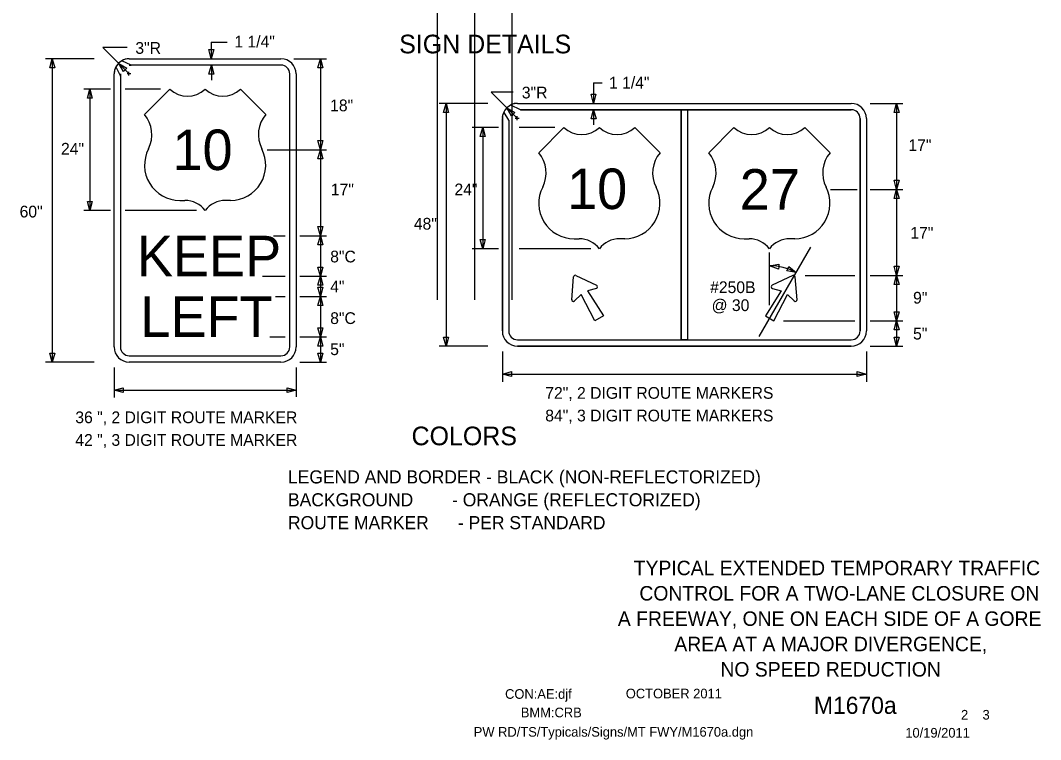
# Model space of a CAD drawing. Extents: x 16715 to 19504, y 7040 to 8495.
# Drawn here: x 17808 to 18464, y 7218 to 7680 of the extents above; entities that cross this region are included whole.
import ezdxf

# ---------------------------------------------------------------- set-up
doc = ezdxf.new("R2010")
doc.units = 0
for name, color, linetype in [('ALI_LEGAL_EX', 7, 'Continuous'), ('BORDER', 7, 'Continuous'), ('BORDER_SIGNAL_WO', 7, 'Continuous'), ('TRAFFIC_SIGNS_PR', 7, 'Continuous'), ('TYPICAL_EX', 7, 'Continuous'), ('TYPICAL_TEXT_DIMEN_PR', 7, 'Continuous')]:
    doc.layers.add(name, color=color, linetype=linetype)

msp = doc.modelspace()

# ---------------------------------------------------------------- linework, layer by layer
at = {"layer": 'ALI_LEGAL_EX'}
for p, q in [((18076.31, 7500.83), (18076.31, 8111.03)), ((18100.31, 7500.83), (18100.31, 8111.03)), ((18124.31, 7500.83), (18124.31, 8111.03))]:
    msp.add_line(p, q, dxfattribs=at)
at = {"layer": 'TRAFFIC_SIGNS_PR'}
for p, q in [((17879.37, 7651.62), (17873.27, 7654.37)), ((17878.16, 7655.69), (17975.66, 7655.69)), ((17868.41, 7470.44), (17868.41, 7645.94)), ((17870.58, 7652.07), (17869.58, 7650.56)), ((17869.6, 7650.49), (17872.48, 7644.45)), ((17872.48, 7645.94), (17872.48, 7470.44)), ((17975.66, 7651.62), (17878.16, 7651.62)), ((17981.35, 7470.44), (17981.35, 7645.94)), ((17985.41, 7645.94), (17985.41, 7470.44)), ((18127.69, 7626.99), (18342.19, 7626.99)), ((18127.69, 7626.99), (18342.19, 7626.99)), ((18118.85, 7621.25), (18121.99, 7616.2)), ((18129.64, 7622.94), (18123.41, 7625.95)), ((18129.62, 7622.93), (18232.9, 7622.93)), ((18342.19, 7622.93), (18129.62, 7622.93)), ((18232.9, 7622.93), (18232.9, 7475.05)), ((18236.97, 7622.93), (18236.97, 7475.05)), ((18236.97, 7622.93), (18342.19, 7622.93)), ((18117.94, 7617.24), (18117.94, 7480.74)), ((18117.94, 7480.74), (18117.94, 7617.24)), ((18122, 7616.19), (18122, 7480.74)), ((18122, 7616.19), (18122, 7480.74)), ((18347.87, 7617.24), (18347.87, 7571.49)), ((18347.87, 7480.74), (18347.87, 7617.24)), ((18351.94, 7617.24), (18351.94, 7480.74)), ((18351.94, 7617.24), (18351.94, 7480.74)), ((18347.87, 7571.49), (18347.87, 7480.74)), ((18162.54, 7500.85), (18163.69, 7515.56)), ((18165.2, 7516.43), (18178.51, 7510.07)), ((18304.67, 7516.43), (18291.35, 7510.07)), ((18307.33, 7500.85), (18306.18, 7515.56)), ((18127.69, 7475.05), (18342.19, 7475.05)), ((18127.69, 7470.99), (18342.19, 7470.99)), ((18342.19, 7470.99), (18127.69, 7470.99)), ((17878.16, 7464.75), (17975.66, 7464.75)), ((17975.66, 7460.69), (17878.16, 7460.69))]:
    msp.add_line(p, q, dxfattribs=at)
for points in [[(18129.62, 7622.93), (18129.61, 7622.93)], [(18121.99, 7616.2), (18122, 7616.19)], [(18178.35, 7508.1), (18172.63, 7506.53), (18182.85, 7490.36), (18177.45, 7487.24), (18168.55, 7504.17), (18164.33, 7500.01)], [(18291.52, 7508.1), (18297.24, 7506.53), (18287.02, 7490.36), (18292.42, 7487.24), (18301.32, 7504.17), (18305.54, 7500.01)]]:
    msp.add_lwpolyline(points, dxfattribs=at)
msp.add_lwpolyline([(18232.9, 7622.93), (18236.97, 7622.93), (18236.97, 7475.05), (18232.9, 7475.05)], close=True, dxfattribs=at)
for centre, radius, start, end in [((17878.16, 7645.94), 9.75, 90, 180), ((17877.58, 7648.11), 7.6, 85.58319, 124.53531), ((17975.66, 7645.94), 9.75, 0, 90), ((17875.45, 7646.53), 7.06, 145.86811, 184.82317), ((17867.02, 7645.19), 5.51, 352.24294, 7.75653), ((17878.77, 7656.05), 4.47, 262.2432, 277.7568), ((17975.66, 7645.94), 5.69, 0, 90), ((18127.69, 7617.24), 9.75, 90, 180), ((18127.69, 7617.24), 9.75, 90, 180), ((18127.01, 7620.42), 6.6, 84.11162, 123.06374), ((18342.19, 7617.24), 9.75, 0, 90), ((18342.19, 7617.24), 9.75, 0, 90), ((18124.07, 7617.94), 6.17, 147.60925, 186.56283), ((18128.63, 7630.11), 7.24, 277.81035, 278.05403), ((18342.19, 7617.24), 5.69, 0, 89.99421), ((18342.19, 7617.24), 5.69, 0, 90), ((18164.74, 7515.48), 1.06, 64.48226, 175.51774), ((18305.13, 7515.48), 1.06, 4.48226, 115.51774), ((18178.06, 7509.12), 1.06, 285.9885, 64.48226), ((18291.81, 7509.12), 1.06, 115.51774, 254.0115), ((18163.59, 7500.77), 1.06, 175.51775, 314.01151), ((18306.28, 7500.77), 1.06, 225.98849, 4.48225), ((18127.69, 7480.74), 9.75, 180, 270), ((18127.69, 7480.74), 9.75, 180, 270), ((18127.69, 7480.74), 5.69, 180, 270), ((18127.69, 7480.74), 5.69, 180, 270), ((18342.19, 7480.74), 9.75, 270, 0), ((18342.19, 7480.74), 5.69, 270, 0), ((18342.19, 7480.74), 9.75, 270, 0), ((18342.19, 7480.74), 5.69, 270, 0), ((17878.16, 7470.44), 9.75, 180, 270), ((17878.16, 7470.44), 5.69, 180, 270), ((17975.66, 7470.44), 5.69, 270, 0), ((17975.66, 7470.44), 9.75, 270, 0)]:
    msp.add_arc(centre, radius, start, end, dxfattribs=at)
at = {"layer": 'TYPICAL_EX'}
for p, q in [((17887.91, 7619.94), (17904.16, 7636.19)), ((17965.92, 7619.94), (17949.66, 7636.19)), ((18141.3, 7595.33), (18157.55, 7611.58)), ((18219.3, 7595.33), (18203.05, 7611.58)), ((18250.57, 7595.33), (18266.82, 7611.58)), ((18328.58, 7595.33), (18312.32, 7611.58)), ((17910.64, 7564.65), (17913.89, 7564.65)), ((17943.19, 7564.65), (17939.94, 7564.65)), ((18164.02, 7540.04), (18167.27, 7540.04)), ((18196.57, 7540.04), (18193.32, 7540.04)), ((18273.3, 7540.04), (18276.55, 7540.04)), ((18305.85, 7540.04), (18302.6, 7540.04))]:
    msp.add_line(p, q, dxfattribs=at)
for centre, radius, start, end in [((17915.54, 7648.02), 16.42, 226.14041, 313.85958), ((17938.29, 7648.02), 16.42, 226.14042, 313.85959), ((17872.51, 7606.93), 20.16, 333.09768, 40.19361), ((17981.31, 7606.93), 20.16, 139.80639, 206.90233), ((18168.92, 7623.41), 16.42, 226.14041, 313.85958), ((18191.67, 7623.41), 16.42, 226.14042, 313.85959), ((18278.2, 7623.41), 16.42, 226.14041, 313.85958), ((18300.95, 7623.41), 16.42, 226.14042, 313.85959), ((17910.68, 7587.37), 22.73, 152.6698, 269.90132), ((17943.15, 7587.37), 22.73, 270.09868, 27.3302), ((18125.9, 7582.31), 20.16, 333.09768, 40.19361), ((18234.7, 7582.31), 20.16, 139.80639, 206.90233), ((18235.17, 7582.31), 20.16, 333.09768, 40.19361), ((18343.98, 7582.31), 20.16, 139.80639, 206.90233), ((18164.06, 7562.76), 22.73, 152.6698, 269.90132), ((18196.53, 7562.76), 22.73, 270.09868, 27.3302), ((18273.34, 7562.76), 22.73, 152.6698, 269.90132), ((18305.81, 7562.76), 22.73, 270.09868, 27.3302), ((17913.93, 7548.37), 16.28, 37.1038, 90.13853), ((17939.9, 7548.37), 16.28, 89.86147, 142.8962), ((18167.31, 7523.76), 16.28, 37.1038, 90.13853), ((18193.28, 7523.76), 16.28, 89.86147, 142.8962), ((18276.59, 7523.76), 16.28, 37.1038, 90.13853), ((18302.56, 7523.76), 16.28, 89.86147, 142.8962)]:
    msp.add_arc(centre, radius, start, end, dxfattribs=at)
at = {"layer": 'TYPICAL_TEXT_DIMEN_PR'}
for p, q in [((17930.88, 7666.45), (17930.88, 7655.69)), ((17930.88, 7666.45), (17940.99, 7666.45)), ((17876.78, 7662.97), (17861.13, 7662.97)), ((17861.13, 7662.97), (17871.36, 7652.73)), ((17930.88, 7655.69), (17929.31, 7661.55)), ((17929.31, 7661.55), (17930.88, 7661.55)), ((17930.88, 7661.55), (17932.46, 7661.55)), ((17932.46, 7661.55), (17930.88, 7655.69)), ((17855.58, 7655.69), (17824.29, 7655.69)), ((17827.06, 7649.82), (17828.63, 7655.69)), ((17828.63, 7655.69), (17828.63, 7460.69)), ((17828.63, 7655.69), (17830.2, 7649.82)), ((17871.36, 7652.73), (17877.92, 7646.18)), ((17874.4, 7647.48), (17871.36, 7652.73)), ((17871.36, 7652.73), (17876.62, 7649.7)), ((17983.95, 7655.69), (18004.91, 7655.69)), ((17999.44, 7649.82), (18001.02, 7655.69)), ((18001.02, 7655.69), (18001.02, 7597.19)), ((18001.02, 7655.69), (18002.59, 7649.82)), ((17828.63, 7649.82), (17827.06, 7649.82)), ((17830.2, 7649.82), (17828.63, 7649.82)), ((17875.51, 7648.59), (17874.4, 7647.48)), ((17876.62, 7649.7), (17875.51, 7648.59)), ((17876.71, 7646.18), (17879.13, 7646.18)), ((17877.92, 7644.97), (17877.92, 7647.39)), ((17929.36, 7645.76), (17930.93, 7651.62)), ((17930.93, 7645.76), (17929.36, 7645.76)), ((17930.93, 7651.62), (17930.93, 7641.87)), ((17930.93, 7651.62), (17932.5, 7645.76)), ((17932.5, 7645.76), (17930.93, 7645.76)), ((18001.02, 7649.82), (17999.44, 7649.82)), ((18002.59, 7649.82), (18001.02, 7649.82)), ((18176.54, 7640.14), (18176.54, 7626.99)), ((18176.54, 7640.14), (18182.07, 7640.14)), ((17866.04, 7636.19), (17848.91, 7636.19)), ((17851.24, 7630.32), (17852.81, 7636.19)), ((17852.81, 7636.19), (17852.81, 7558.19)), ((17852.81, 7636.19), (17854.38, 7630.32)), ((17898.28, 7636.19), (17875.4, 7636.19)), ((18124.83, 7634.27), (18110.65, 7634.27)), ((18110.65, 7634.27), (18120.8, 7624.12)), ((18176.54, 7626.99), (18174.97, 7632.85)), ((18174.97, 7632.85), (18176.54, 7632.85)), ((18176.54, 7632.85), (18178.11, 7632.85)), ((18178.11, 7632.85), (18176.54, 7626.99)), ((17852.81, 7630.32), (17851.24, 7630.32)), ((17854.38, 7630.32), (17852.81, 7630.32)), ((18108.7, 7626.99), (18077.41, 7626.99)), ((18080.18, 7621.13), (18081.75, 7626.99)), ((18081.75, 7626.99), (18081.75, 7470.99)), ((18081.75, 7626.99), (18083.32, 7621.13)), ((18354.31, 7626.99), (18375.27, 7626.99)), ((18369.8, 7621.13), (18371.37, 7626.99)), ((18371.37, 7626.99), (18371.37, 7571.74)), ((18371.37, 7626.99), (18372.94, 7621.13)), ((18081.75, 7621.13), (18080.18, 7621.13)), ((18083.32, 7621.13), (18081.75, 7621.13)), ((18120.8, 7624.12), (18127.44, 7617.48)), ((18123.83, 7618.87), (18120.8, 7624.12)), ((18120.8, 7624.12), (18126.05, 7621.09)), ((18124.94, 7619.98), (18123.83, 7618.87)), ((18126.05, 7621.09), (18124.94, 7619.98)), ((18175.02, 7617.06), (18176.59, 7622.93)), ((18175.02, 7617.06), (18176.59, 7622.93)), ((18176.59, 7622.93), (18176.59, 7613.18)), ((18176.59, 7622.93), (18178.16, 7617.06)), ((18176.59, 7622.93), (18178.16, 7617.06)), ((18371.37, 7621.13), (18369.8, 7621.13)), ((18372.94, 7621.13), (18371.37, 7621.13)), ((18126.24, 7617.48), (18128.65, 7617.48)), ((18127.44, 7616.27), (18127.44, 7618.69)), ((18176.59, 7617.06), (18175.02, 7617.06)), ((18176.59, 7617.06), (18175.02, 7617.06)), ((18178.16, 7617.06), (18176.59, 7617.06)), ((18178.16, 7617.06), (18176.59, 7617.06)), ((18115.56, 7611.58), (18098.44, 7611.58)), ((18103.73, 7605.71), (18105.3, 7611.58)), ((18105.3, 7611.58), (18105.3, 7533.58)), ((18105.3, 7611.58), (18106.87, 7605.71)), ((18151.66, 7611.58), (18128.79, 7611.58)), ((18001.02, 7597.19), (17999.44, 7603.05)), ((17999.44, 7603.05), (18001.02, 7603.05)), ((18001.02, 7603.05), (18002.59, 7603.05)), ((18002.59, 7603.05), (18001.02, 7597.19)), ((18105.3, 7605.71), (18103.73, 7605.71)), ((18106.87, 7605.71), (18105.3, 7605.71)), ((17966.8, 7597.19), (18004.91, 7597.19)), ((17999.44, 7591.32), (18001.02, 7597.19)), ((18001.02, 7597.19), (18001.02, 7541.94)), ((18001.02, 7597.19), (18002.59, 7591.32)), ((18001.02, 7591.32), (17999.44, 7591.32)), ((18002.59, 7591.32), (18001.02, 7591.32)), ((18371.37, 7571.74), (18369.8, 7577.6)), ((18369.8, 7577.6), (18371.37, 7577.6)), ((18371.37, 7577.6), (18372.94, 7577.6)), ((18372.94, 7577.6), (18371.37, 7571.74)), ((18328.75, 7571.74), (18345.9, 7571.74)), ((18354.31, 7571.74), (18375.27, 7571.74)), ((18369.8, 7565.88), (18371.37, 7571.74)), ((18371.37, 7571.74), (18371.37, 7516.49)), ((18371.37, 7571.74), (18372.94, 7565.88)), ((17852.81, 7558.19), (17851.24, 7564.05)), ((17851.24, 7564.05), (17852.81, 7564.05)), ((17852.81, 7564.05), (17854.38, 7564.05)), ((17854.38, 7564.05), (17852.81, 7558.19)), ((18371.37, 7565.88), (18369.8, 7565.88)), ((18372.94, 7565.88), (18371.37, 7565.88)), ((17866.04, 7558.19), (17848.91, 7558.19)), ((17921.4, 7558.19), (17875.4, 7558.19)), ((18001.02, 7541.94), (17999.44, 7547.8)), ((17999.44, 7547.8), (18001.02, 7547.8)), ((18001.02, 7547.8), (18002.59, 7547.8)), ((18002.59, 7547.8), (18001.02, 7541.94)), ((17970.74, 7541.94), (17978.42, 7541.94)), ((17987.78, 7541.94), (18004.91, 7541.94)), ((17999.44, 7536.07), (18001.02, 7541.94)), ((18001.02, 7541.94), (18001.02, 7515.94)), ((18001.02, 7541.94), (18002.59, 7536.07)), ((18001.02, 7536.07), (17999.44, 7536.07)), ((18002.59, 7536.07), (18001.02, 7536.07)), ((18105.3, 7533.58), (18103.73, 7539.44)), ((18103.73, 7539.44), (18105.3, 7539.44)), ((18105.3, 7539.44), (18106.87, 7539.44)), ((18106.87, 7539.44), (18105.3, 7533.58)), ((18282.97, 7477.09), (18316.21, 7534.68)), ((18115.56, 7533.58), (18098.44, 7533.58)), ((18174.79, 7533.58), (18128.79, 7533.58)), ((18289.72, 7497.24), (18289.72, 7531.24)), ((18001.02, 7515.94), (17999.44, 7521.8)), ((17999.44, 7521.8), (18001.02, 7521.8)), ((18001.02, 7521.8), (18002.59, 7521.8)), ((18002.59, 7521.8), (18001.02, 7515.94)), ((18289.75, 7522.68), (18295.74, 7523.64)), ((18295.42, 7520.52), (18289.75, 7522.68)), ((18295.58, 7522.08), (18295.42, 7520.52)), ((18295.74, 7523.64), (18295.58, 7522.08)), ((18301.42, 7520.77), (18302.1, 7522.19)), ((18302.1, 7522.19), (18306.7, 7518.23)), ((18371.37, 7516.49), (18369.8, 7522.35)), ((18369.8, 7522.35), (18371.37, 7522.35)), ((18371.37, 7522.35), (18372.94, 7522.35)), ((18372.94, 7522.35), (18371.37, 7516.49)), ((17963.72, 7515.94), (17978.42, 7515.94)), ((17987.78, 7515.94), (18004.91, 7515.94)), ((17999.44, 7510.07), (18001.02, 7515.94)), ((18001.02, 7515.94), (18001.02, 7502.94)), ((18001.02, 7515.94), (18002.59, 7510.07)), ((18300.74, 7519.36), (18301.42, 7520.77)), ((18306.7, 7518.23), (18300.74, 7519.36)), ((18312.67, 7516.49), (18344.54, 7516.49)), ((18354.31, 7516.49), (18375.27, 7516.49)), ((18369.8, 7510.63), (18371.37, 7516.49)), ((18371.37, 7516.49), (18371.37, 7487.24)), ((18371.37, 7516.49), (18372.94, 7510.63)), ((18001.02, 7510.07), (17999.44, 7510.07)), ((18001.02, 7502.94), (17999.44, 7508.8)), ((17999.44, 7508.8), (18001.02, 7508.8)), ((18002.59, 7510.07), (18001.02, 7510.07)), ((18001.02, 7508.8), (18002.59, 7508.8)), ((18002.59, 7508.8), (18001.02, 7502.94)), ((18371.37, 7510.63), (18369.8, 7510.63)), ((18372.94, 7510.63), (18371.37, 7510.63)), ((17972.08, 7502.94), (17978.42, 7502.94)), ((17987.78, 7502.94), (18004.91, 7502.94)), ((17999.44, 7497.07), (18001.02, 7502.94)), ((18001.02, 7502.94), (18001.02, 7476.94)), ((18001.02, 7502.94), (18002.59, 7497.07)), ((18001.02, 7497.07), (17999.44, 7497.07)), ((18002.59, 7497.07), (18001.02, 7497.07)), ((18371.37, 7487.24), (18369.8, 7493.1)), ((18369.8, 7493.1), (18371.37, 7493.1)), ((18371.37, 7493.1), (18372.94, 7493.1)), ((18372.94, 7493.1), (18371.37, 7487.24)), ((18001.02, 7476.94), (17999.44, 7482.8)), ((17999.44, 7482.8), (18001.02, 7482.8)), ((18001.02, 7482.8), (18002.59, 7482.8)), ((18002.59, 7482.8), (18001.02, 7476.94)), ((18298.54, 7487.24), (18344.54, 7487.24)), ((18354.31, 7487.24), (18375.27, 7487.24)), ((18369.8, 7481.38), (18371.37, 7487.24)), ((18371.37, 7487.24), (18371.37, 7470.99)), ((18371.37, 7487.24), (18372.94, 7481.38)), ((17968.58, 7476.94), (17978.42, 7476.94)), ((17987.78, 7476.94), (18004.91, 7476.94)), ((17999.44, 7471.07), (18001.02, 7476.94)), ((18001.02, 7476.94), (18001.02, 7460.69)), ((18001.02, 7476.94), (18002.59, 7471.07)), ((18081.75, 7470.99), (18080.18, 7476.85)), ((18080.18, 7476.85), (18081.75, 7476.85)), ((18081.75, 7476.85), (18083.32, 7476.85)), ((18083.32, 7476.85), (18081.75, 7470.99)), ((18371.37, 7481.38), (18369.8, 7481.38)), ((18371.37, 7470.99), (18369.8, 7476.85)), ((18369.8, 7476.85), (18371.37, 7476.85)), ((18372.94, 7481.38), (18371.37, 7481.38)), ((18371.37, 7476.85), (18372.94, 7476.85)), ((18372.94, 7476.85), (18371.37, 7470.99)), ((18001.02, 7471.07), (17999.44, 7471.07)), ((18002.59, 7471.07), (18001.02, 7471.07)), ((18108.7, 7470.99), (18077.41, 7470.99)), ((18354.31, 7470.99), (18371.44, 7470.99)), ((18354.31, 7470.99), (18375.27, 7470.99)), ((18354.31, 7470.99), (18371.44, 7470.99)), ((17828.63, 7460.69), (17827.06, 7466.55)), ((17827.06, 7466.55), (17828.63, 7466.55)), ((17828.63, 7466.55), (17830.2, 7466.55)), ((17830.2, 7466.55), (17828.63, 7460.69)), ((18001.02, 7460.69), (17999.44, 7466.55)), ((17999.44, 7466.55), (18001.02, 7466.55)), ((18001.02, 7466.55), (18002.59, 7466.55)), ((18002.59, 7466.55), (18001.02, 7460.69)), ((18117.94, 7467.64), (18117.94, 7448.08)), ((18351.94, 7467.64), (18351.94, 7448.08)), ((17855.58, 7460.69), (17824.29, 7460.69)), ((17868.41, 7457.34), (17868.41, 7437.99)), ((17985.41, 7457.34), (17985.41, 7438.45)), ((17987.78, 7460.69), (18004.91, 7460.69)), ((18117.94, 7453.02), (18123.8, 7454.59)), ((18117.94, 7453.02), (18351.94, 7453.02)), ((18123.8, 7451.44), (18117.94, 7453.02)), ((18123.8, 7454.59), (18123.8, 7453.02)), ((18123.8, 7453.02), (18123.8, 7451.44)), ((18346.07, 7453.02), (18346.07, 7454.59)), ((18346.07, 7454.59), (18351.94, 7453.02)), ((18351.94, 7453.02), (18346.07, 7451.44)), ((18346.07, 7451.44), (18346.07, 7453.02)), ((17868.41, 7442.71), (17874.28, 7444.28)), ((17868.41, 7442.71), (17985.41, 7442.71)), ((17874.28, 7441.14), (17868.41, 7442.71)), ((17874.28, 7444.28), (17874.28, 7442.71)), ((17874.28, 7442.71), (17874.28, 7441.14)), ((17979.55, 7442.71), (17979.55, 7444.28)), ((17979.55, 7444.28), (17985.41, 7442.71)), ((17985.41, 7442.71), (17979.55, 7441.14)), ((17979.55, 7441.14), (17979.55, 7442.71))]:
    msp.add_line(p, q, dxfattribs=at)
msp.add_arc((18289.92, 7488.24), 34.39, 60.74521, 90.32117, dxfattribs=at)

# ---------------------------------------------------------------- texts
at = {"layer": 'BORDER'}
for s, p in [('TYPICAL EXTENDED TEMPORARY TRAFFIC', (18202.38, 7323.77)), ('CONTROL FOR A TWO-LANE CLOSURE ON', (18206.02, 7307.48)), ('A FREEWAY, ONE ON EACH SIDE OF A GORE', (18192.17, 7291.19)), ('AREA AT A MAJOR DIVERGENCE,', (18228.49, 7274.9)), ('NO SPEED REDUCTION', (18258.11, 7258.61))]:
    msp.add_text(s, height=9.3, dxfattribs=at).set_placement(p)
at = {"layer": 'BORDER_SIGNAL_WO'}
for s, height, p in [('CON:AE:djf  ', 6.2, (18119.69, 7244.31)), ('    OCTOBER 2011    ', 6.2, (18188.08, 7244.59)), ('    M1670a   ', 11, (18301.86, 7234.63)), ('BMM:CRB   ', 6.2, (18129.81, 7232.42)), (' 2    3 ', 6.2, (18410.45, 7230.95)), ('PW RD/TS/Typicals/Signs/MT FWY/M1670a.dgn      ', 6.2, (18099.55, 7219.96)), ('10/19/2011    ', 6.2, (18376.93, 7219.38))]:
    msp.add_text(s, height=height, dxfattribs=at).set_placement(p)
at = {"layer": 'TRAFFIC_SIGNS_PR'}
for s, p in [('10', (17905.89, 7584.19)), ('10', (18159.53, 7559.12)), ('27', (18270.54, 7558.76)), ('KEEP', (17883.02, 7515.94)), ('LEFT', (17885.25, 7476.94))]:
    msp.add_text(s, height=26, dxfattribs=at).set_placement(p)
at = {"layer": 'TYPICAL_TEXT_DIMEN_PR'}
for s, height, p in [('3"R', 7.55, (17882.05, 7658.85)), ('1 1/4"', 7.55, (17945.69, 7662.94)), ('SIGN DETAILS', 12, (18051.64, 7659.16)), ('1 1/4"', 7.55, (18186.47, 7636.56)), ('3"R', 7.55, (18130.47, 7630.19)), ('18"', 7.55, (18007.25, 7621.95)), ('24"', 7.55, (17834.26, 7594.07)), ('17"', 7.55, (18378.94, 7596.35)), ('17"', 7.55, (18007.71, 7567.91)), ('24"', 7.55, (18087.16, 7567.91)), ('60"', 7.55, (17807.66, 7553.7)), ('48"', 7.55, (18061.05, 7545.89)), ('17"', 7.55, (18380.15, 7539.99)), ('8"C', 7.55, (18007.29, 7524.79)), ('4" ', 7.55, (18007.29, 7505.53)), ('#250B', 7.55, (18251.49, 7505.08)), ('9"', 7.55, (18381.93, 7498.33)), ('@ 30', 7.55, (18252.44, 7493.53)), ('8"C', 7.55, (18007.29, 7485.2)), ('5"', 7.55, (18381.92, 7475.23)), ('5" ', 7.55, (18007.29, 7465.23)), ('72", 2 DIGIT ROUTE MARKERS', 7.55, (18145.51, 7437.15)), ('84", 3 DIGIT ROUTE MARKERS', 7.55, (18145.51, 7422.6)), ('36 ", 2 DIGIT ROUTE MARKER', 7.55, (17843.46, 7421.45)), ('COLORS', 12, (18059.58, 7407.27)), ('42 ", 3 DIGIT ROUTE MARKER', 7.55, (17843.46, 7406.9)), ('LEGEND AND BORDER - BLACK (NON-REFLECTORIZED)', 8.4, (17980.15, 7382.74)), ('BACKGROUND        - ORANGE (REFLECTORIZED)', 8.4, (17980.15, 7368.04)), ('ROUTE MARKER      - PER STANDARD', 8.4, (17980.15, 7353.34))]:
    msp.add_text(s, height=height, dxfattribs=at).set_placement(p)

doc.saveas('drawing.dxf')
